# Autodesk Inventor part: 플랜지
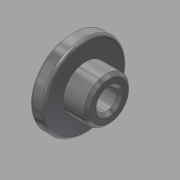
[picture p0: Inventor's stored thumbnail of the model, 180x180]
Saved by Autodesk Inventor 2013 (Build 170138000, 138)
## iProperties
Created: 2018-01
Part Number: 플랜지
Material: 스테인리스강
Document SubType Name: Modeling
Designer: mduedu
Density: 1 g/cm^3
Author: mduedu
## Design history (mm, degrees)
sketch "스케치1"
  geometry: L1 (0, 0)-(0, 7); L2 (0, 7)-(2.5, 7); L3 (2.5, 7)-(2.5, 3.75); L4 (2.5, 3.75)-(6.5, 3.75); L5 (6.5, 3.75)-(6.5, 0); L6 (6.5, 0)-(0, 0)
  constraints: 12 end point, 4 parallel, 1 perpendicular, 1 vertical
  dimensions: "d0" = 14 diameter of L2 L6; "d2" = 7.5 diameter of L4 L6; "d3" = 2.5 distance of L1.end L2.end; "d4" = 6.5 distance between parallel lines of L5 L1
revolve "회전1" sketch "스케치1" stored, may be unused: angle "d5" = 90 deg
hole "구멍1" diameter "d8" = 3.5; stored, may be unused: countersink angle "d12" = 90 deg, drill point angle "d14" = 118 deg; dims "d9" = 6, "d10" = 4, "d11" = 2, "d13" = 8, "d19" = 10, "d20" = 10
fillet "모깎기1" dims "d15" = 0.5
chamfer "모따기1" distance "d16" = 0.5; stored, may be unused: second distance "d17" = 2, angle "d18" = 45 deg
chamfer "모따기2" distance "d21" = 0.5; stored, may be unused: second distance "d22" = 2, angle "d23" = 45 deg
node "솔리드1"
